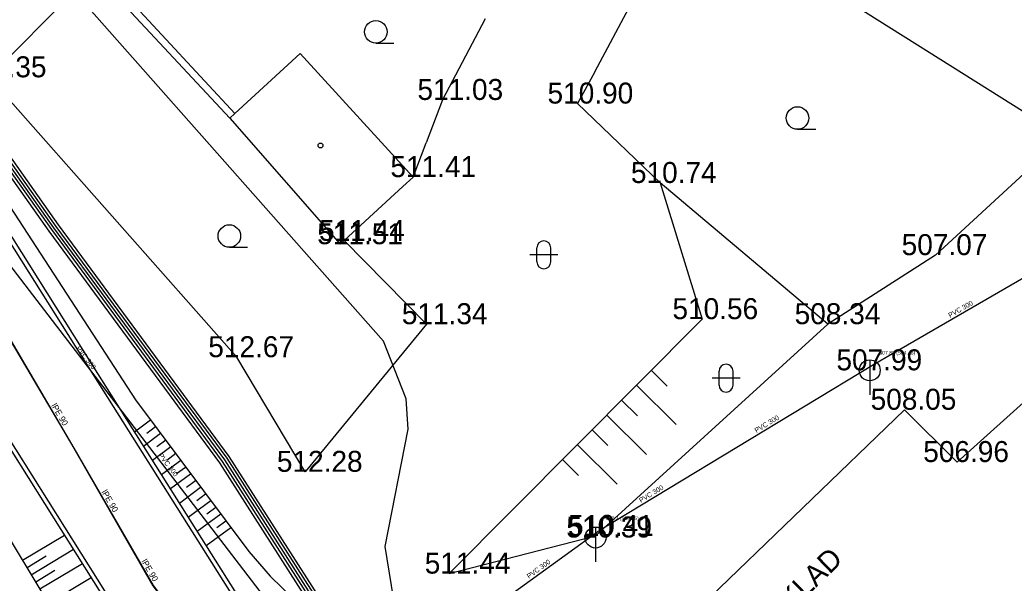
# Model space of a CAD drawing. Extents: x -668867 to -667827, y -1131943 to -1131019.
# Drawn here: x -668363.35 to -668327.77, y -1131384.01 to -1131363.87 of the extents above; entities that cross this region are included whole.
import ezdxf

# ---------------------------------------------------------------- set-up
doc = ezdxf.new("R2010")
doc.units = 0
for name, color, linetype in [('G_Bod_tecka', 7, 'Continuous'), ('G_Bod_vyska', 7, 'Continuous'), ('G_Breh_Teren', 7, 'Continuous'), ('G_Budovy-znacky', 7, 'Continuous'), ('G_Budovy_Objekty', 7, 'Continuous'), ('G_Budovy_vstupy', 7, 'Continuous'), ('G_Cesty_Schody', 7, 'Continuous'), ('G_Plochy_zpevnene', 7, 'Continuous'), ('G_Ploty', 7, 'Continuous'), ('G_Ploty_vstupy', 7, 'Continuous'), ('G_Poznamky_odkaz', 7, 'Continuous'), ('G_Site-kanalizace', 7, 'Continuous'), ('G_Vyskove_srafy', 7, 'Continuous'), ('G_Z_CHRANICKA-TEPLOVOD_kotovane', 7, 'Continuous'), ('G_Z_ELsilove_podz_kotovane', 7, 'Continuous'), ('G_Z_ELsilove_zrusene', 7, 'Continuous'), ('G_Z_KANAL_podz_kotovane', 7, 'Continuous'), ('G_Z_SPOJE_podz_kotovane', 7, 'Continuous'), ('G_Z_VODA_podz_kotovane', 7, 'Continuous'), ('G_Zelen-Znacky', 7, 'Continuous'), ('Vrstva 13', 7, 'Continuous'), ('Vrstva 2', 7, 'Continuous'), ('Vrstva 26', 7, 'Continuous'), ('Vrstva 3', 7, 'Continuous'), ('Vrstva 4', 7, 'Continuous'), ('Vrstva 8', 7, 'Continuous')]:
    doc.layers.add(name, color=color, linetype=linetype)

msp = doc.modelspace()

# ---------------------------------------------------------------- linework, layer by layer
at = {"layer": 'G_Bod_tecka'}
for p, q in [((-668348.22, -1131366.73), (-668348.22, -1131366.73)), ((-668343.4, -1131366.86), (-668343.4, -1131366.86)), ((-668349.27, -1131369.49), (-668349.27, -1131369.49)), ((-668340.44, -1131369.7), (-668340.44, -1131369.7)), ((-668351.89, -1131371.89), (-668351.89, -1131371.89)), ((-668351.76, -1131371.77), (-668351.76, -1131371.77)), ((-668330.59, -1131372.28), (-668330.59, -1131372.28)), ((-668348.8, -1131374.75), (-668348.8, -1131374.75)), ((-668338.94, -1131374.57), (-668338.94, -1131374.57)), ((-668334.44, -1131374.75), (-668334.44, -1131374.75)), ((-668355.58, -1131375.93), (-668355.58, -1131375.93)), ((-668332.94, -1131376.4), (-668332.94, -1131376.4)), ((-668331.7, -1131377.81), (-668331.7, -1131377.81)), ((-668329.81, -1131379.68), (-668329.81, -1131379.68)), ((-668353.14, -1131380.03), (-668353.14, -1131380.03)), ((-668342.75, -1131382.32), (-668342.75, -1131382.32)), ((-668342.75, -1131382.38), (-668342.75, -1131382.38)), ((-668347.99, -1131383.67), (-668347.99, -1131383.67))]:
    msp.add_line(p, q, dxfattribs=at)
at = {"layer": 'G_Breh_Teren'}
for p, q in [((-668364.19, -1131369.81), (-668359.21, -1131377.46)), ((-668338.94, -1131374.57), (-668347.99, -1131383.67)), ((-668342.75, -1131382.32), (-668334.44, -1131374.75)), ((-668359.21, -1131377.46), (-668355.16, -1131382.88)), ((-668358.86, -1131390.44), (-668364.64, -1131380.88)), ((-668347.99, -1131383.67), (-668342.75, -1131382.32))]:
    msp.add_line(p, q, dxfattribs=at)
for points in [[(-668340.44, -1131369.7), (-668338.94, -1131374.57)], [(-668355.16, -1131382.88), (-668354.39, -1131383.76), (-668353.55, -1131384.59), (-668352.66, -1131385.35), (-668351.73, -1131386.06), (-668350.74, -1131386.69), (-668349.72, -1131387.26), (-668348.66, -1131387.76), (-668347.57, -1131388.18), (-668346.45, -1131388.53), (-668345.31, -1131388.8), (-668344.15, -1131389), (-668342.99, -1131389.11), (-668342.38, -1131389.14)]]:
    msp.add_lwpolyline(points, dxfattribs=at)
at = {"layer": 'G_Budovy-znacky'}
msp.add_circle((-668352.59, -1131368.36), 0.0875, dxfattribs=at)
at = {"layer": 'G_Budovy_Objekty'}
for p, q in [((-668353.32, -1131365.07), (-668355.65, -1131367.21)), ((-668353.32, -1131365.07), (-668349.27, -1131369.49)), ((-668355.65, -1131367.21), (-668355.83, -1131367.38)), ((-668355.83, -1131367.38), (-668351.89, -1131371.89)), ((-668349.64, -1131369.82), (-668349.27, -1131369.49)), ((-668351.74, -1131371.76), (-668351.44, -1131371.48)), ((-668351.89, -1131371.89), (-668351.74, -1131371.76)), ((-668329.81, -1131379.68), (-668325.18, -1131375.51)), ((-668342.74, -1131388.45), (-668331.7, -1131377.81)), ((-668331.7, -1131377.81), (-668329.81, -1131379.68))]:
    msp.add_line(p, q, dxfattribs=at)
at = {"layer": 'G_Budovy_vstupy'}
msp.add_line((-668351.44, -1131371.48), (-668349.64, -1131369.82), dxfattribs=at)
at = {"layer": 'G_Cesty_Schody'}
for points in [[(-668355.04, -1131385.56), (-668360.89, -1131376.27), (-668365.67, -1131368.69), (-668366.59, -1131367.37), (-668378.77, -1131351.46), (-668388.76, -1131338.33)], [(-668391.56, -1131341.09), (-668381.8, -1131353.8), (-668369.6, -1131369.69), (-668368.3, -1131371.62), (-668363.5, -1131379.22), (-668357.66, -1131388.52)]]:
    msp.add_lwpolyline(points, dxfattribs=at)
at = {"layer": 'G_Plochy_zpevnene'}
for points in [[(-668354.91, -1131385.48), (-668360.76, -1131376.19), (-668365.54, -1131368.6), (-668366.47, -1131367.28), (-668378.65, -1131351.37), (-668388.64, -1131338.24)], [(-668392.25, -1131341.82), (-668391.58, -1131341.3), (-668381.92, -1131353.89), (-668369.72, -1131369.78), (-668368.43, -1131371.71), (-668363.63, -1131379.3), (-668357.79, -1131388.6)]]:
    msp.add_lwpolyline(points, dxfattribs=at)
at = {"layer": 'G_Ploty'}
for p, q in [((-668339.43, -1131359.6), (-668326, -1131368.05)), ((-668355.65, -1131367.21), (-668360.52, -1131361.98)), ((-668360.71, -1131362.15), (-668355.83, -1131367.38)), ((-668364.45, -1131365.92), (-668361.63, -1131363.08)), ((-668346.7, -1131363.83), (-668348.22, -1131366.73)), ((-668355.58, -1131375.93), (-668364.45, -1131365.92)), ((-668348.22, -1131366.73), (-668348.81, -1131368.27)), ((-668340.44, -1131369.7), (-668343.4, -1131366.86)), ((-668326, -1131368.05), (-668330.59, -1131372.28)), ((-668334.44, -1131374.75), (-668340.44, -1131369.7)), ((-668351.74, -1131371.76), (-668348.8, -1131374.75)), ((-668330.59, -1131372.28), (-668334.44, -1131374.75)), ((-668348.8, -1131374.75), (-668353.14, -1131380.03)), ((-668353.14, -1131380.03), (-668355.58, -1131375.93))]:
    msp.add_line(p, q, dxfattribs=at)
msp.add_lwpolyline([(-668342.78, -1131365.72), (-668339.87, -1131360.27), (-668339.43, -1131359.6)], dxfattribs=at)
at = {"layer": 'G_Ploty_vstupy'}
for p, q in [((-668342.78, -1131365.72), (-668343.4, -1131366.86)), ((-668349.27, -1131369.49), (-668348.81, -1131368.27))]:
    msp.add_line(p, q, dxfattribs=at)
at = {"layer": 'G_Site-kanalizace'}
for p, q in [((-668332.94, -1131376.025), (-668332.94, -1131377.275)), ((-668342.75, -1131382.005), (-668342.75, -1131383.255))]:
    msp.add_line(p, q, dxfattribs=at)
for centre in [(-668332.94, -1131376.4), (-668342.75, -1131382.38)]:
    msp.add_circle(centre, 0.375, dxfattribs=at)
at = {"layer": 'G_Vyskove_srafy'}
for p, q in [((-668340.76, -1131376.4), (-668340.19, -1131376.97)), ((-668341.29, -1131376.93), (-668339.87, -1131378.34)), ((-668341.82, -1131377.47), (-668341.25, -1131378.03)), ((-668342.34, -1131378), (-668340.93, -1131379.41)), ((-668358.67, -1131378.18), (-668359.24, -1131378.61)), ((-668358.31, -1131378.66), (-668358.92, -1131379.12)), ((-668358.49, -1131378.42), (-668358.81, -1131378.66)), ((-668342.87, -1131378.53), (-668342.31, -1131379.09)), ((-668358.13, -1131378.9), (-668358.45, -1131379.14)), ((-668343.4, -1131379.06), (-668341.98, -1131380.47)), ((-668357.95, -1131379.14), (-668358.6, -1131379.63)), ((-668357.77, -1131379.38), (-668358.09, -1131379.62)), ((-668357.59, -1131379.62), (-668358.28, -1131380.14)), ((-668343.93, -1131379.59), (-668343.36, -1131380.16)), ((-668357.24, -1131380.11), (-668357.96, -1131380.64)), ((-668357.42, -1131379.87), (-668357.74, -1131380.1)), ((-668357.06, -1131380.35), (-668357.38, -1131380.59)), ((-668356.88, -1131380.59), (-668357.64, -1131381.16)), ((-668356.7, -1131380.83), (-668357.02, -1131381.07)), ((-668356.52, -1131381.07), (-668357.32, -1131381.66)), ((-668356.16, -1131381.55), (-668357, -1131382.17)), ((-668356.34, -1131381.31), (-668356.66, -1131381.55)), ((-668355.98, -1131381.79), (-668356.3, -1131382.03)), ((-668355.8, -1131382.03), (-668356.68, -1131382.68)), ((-668363.25, -1131383.19), (-668361.75, -1131382.29)), ((-668362.94, -1131383.71), (-668361.43, -1131382.8)), ((-668363.09, -1131383.45), (-668362.41, -1131383.04)), ((-668362.63, -1131384.22), (-668361.11, -1131383.31)), ((-668362.78, -1131383.96), (-668362.1, -1131383.55)), ((-668362.32, -1131384.73), (-668360.8, -1131383.81))]:
    msp.add_line(p, q, dxfattribs=at)
at = {"layer": 'G_Z_CHRANICKA-TEPLOVOD_kotovane'}
msp.add_lwpolyline([(-668366.49, -1131364.819), (-668361.978, -1131371.193), (-668355.865, -1131379.487), (-668350.614, -1131387.7), (-668350.613, -1131387.701), (-668349.219, -1131389.792), (-668342.973, -1131397.546), (-668337.629, -1131404.464), (-668337.551, -1131404.399), (-668337.188, -1131404.096), (-668336.932, -1131404.404), (-668337.307, -1131404.716), (-668337.691, -1131405.036), (-668343.287, -1131397.794), (-668349.541, -1131390.028), (-668350.946, -1131387.92), (-668350.947, -1131387.919), (-668356.195, -1131379.713), (-668362.302, -1131371.427), (-668366.81, -1131365.061)], dxfattribs=at)
at = {"layer": 'G_Z_ELsilove_podz_kotovane'}
for points in [[(-668408.95, -1131333.1), (-668406.83, -1131330.34), (-668406.29, -1131329.53), (-668406.257, -1131329.495), (-668405.49, -1131328.67), (-668399.24, -1131323.79), (-668397.09, -1131324.16), (-668396.08, -1131324.9), (-668391.49, -1131330.34), (-668386.5, -1131336.42), (-668385.67, -1131337.67), (-668385.49, -1131339.6), (-668385.39, -1131341.8), (-668384.66, -1131342.96), (-668373.89, -1131355.96), (-668366.65, -1131364.94), (-668362.14, -1131371.31), (-668356.03, -1131379.6), (-668350.78, -1131387.81), (-668349.38, -1131389.91), (-668343.13, -1131397.67), (-668337.721, -1131404.671), (-668337.216, -1131404.25), (-668337.06, -1131404.25)], [(-668366.73, -1131365), (-668362.221, -1131371.369), (-668356.112, -1131379.657), (-668350.864, -1131387.865), (-668349.461, -1131389.969), (-668343.209, -1131397.732), (-668336.778, -1131406.053), (-668329.236, -1131414.915), (-668325.613, -1131419.198), (-668318.049, -1131426.672), (-668308.959, -1131435.142)], [(-668366.57, -1131364.88), (-668362.059, -1131371.251), (-668355.948, -1131379.543), (-668350.696, -1131387.755), (-668349.299, -1131389.851), (-668343.051, -1131397.608), (-668336.622, -1131405.927), (-668329.084, -1131414.785), (-668325.467, -1131419.062), (-668317.911, -1131426.528), (-668308.821, -1131434.998)]]:
    msp.add_lwpolyline(points, dxfattribs=at)
at = {"layer": 'G_Z_ELsilove_zrusene'}
msp.add_lwpolyline([(-668307.243, -1131431.203), (-668317.995, -1131419.84), (-668326.659, -1131411.121), (-668334.853, -1131402.182), (-668341.39, -1131394.475), (-668345.534, -1131389.961), (-668348.109, -1131387.508), (-668349.338, -1131386.039), (-668349.614, -1131385.544), (-668349.891, -1131385.05), (-668350.277, -1131382.705), (-668349.451, -1131378.507), (-668349.526, -1131377.414), (-668350.334, -1131375.359), (-668361.51, -1131362.724), (-668372.64, -1131350.72)], dxfattribs=at)
msp.add_lwpolyline([(-668307.243, -1131431.203), (-668317.995, -1131419.84), (-668326.659, -1131411.121), (-668334.853, -1131402.182), (-668341.39, -1131394.475), (-668345.534, -1131389.961), (-668348.109, -1131387.508), (-668349.338, -1131386.039), (-668349.614, -1131385.544), (-668349.891, -1131385.05), (-668350.277, -1131382.705), (-668349.451, -1131378.507), (-668349.526, -1131377.414), (-668350.334, -1131375.359), (-668361.51, -1131362.724), (-668372.64, -1131350.72)], dxfattribs=at)
at = {"layer": 'G_Z_KANAL_podz_kotovane'}
for p, q in [((-668377.82, -1131354.24), (-668351.51, -1131388.55)), ((-668342.59, -1131382.11), (-668332.8, -1131376.19)), ((-668351.51, -1131388.55), (-668342.59, -1131382.11))]:
    msp.add_line(p, q, dxfattribs=at)
msp.add_lwpolyline([(-668332.8, -1131376.19), (-668325.98, -1131372.25), (-668320.61, -1131365.08)], dxfattribs=at)
at = {"layer": 'G_Z_SPOJE_podz_kotovane'}
for points in [[(-668366.491, -1131364.82), (-668361.978, -1131371.193), (-668355.865, -1131379.486), (-668350.612, -1131387.7), (-668349.218, -1131389.791), (-668342.973, -1131397.546), (-668336.544, -1131405.864), (-668329.008, -1131414.72), (-668325.393, -1131418.994), (-668317.841, -1131426.455), (-668308.752, -1131434.926)], [(-668366.65, -1131364.94), (-668362.14, -1131371.31), (-668356.03, -1131379.6), (-668350.78, -1131387.81), (-668349.38, -1131389.91), (-668343.13, -1131397.67), (-668336.7, -1131405.99), (-668329.16, -1131414.85), (-668325.54, -1131419.13), (-668317.98, -1131426.6), (-668308.89, -1131435.07)], [(-668366.65, -1131364.94), (-668362.14, -1131371.31), (-668356.03, -1131379.6), (-668350.78, -1131387.81), (-668349.38, -1131389.91), (-668343.13, -1131397.67), (-668336.7, -1131405.99), (-668329.16, -1131414.85), (-668325.54, -1131419.13), (-668317.98, -1131426.6), (-668308.89, -1131435.07)]]:
    msp.add_lwpolyline(points, dxfattribs=at)
at = {"layer": 'G_Z_VODA_podz_kotovane'}
msp.add_lwpolyline([(-668371.54, -1131366.16), (-668371.4, -1131366.07), (-668370.38, -1131365.25), (-668367.57, -1131368.89), (-668364.45, -1131374.04), (-668361.42, -1131379.18), (-668358.58, -1131384.1), (-668354.88, -1131388.99), (-668350.92, -1131393.63), (-668343.05, -1131402.42), (-668337.87, -1131408.31), (-668331.71, -1131415.7), (-668327.79, -1131420.6)], dxfattribs=at)
at = {"layer": 'G_Zelen-Znacky'}
for p, q in [((-668350.612, -1131364.7), (-668349.962, -1131364.697)), ((-668335.522, -1131367.78), (-668334.872, -1131367.777)), ((-668355.852, -1131372), (-668355.202, -1131371.997)), ((-668338.33, -1131376.93), (-668338.33, -1131376.43)), ((-668337.83, -1131376.93), (-668337.83, -1131376.43)), ((-668337.58, -1131376.68), (-668338.58, -1131376.68))]:
    msp.add_line(p, q, dxfattribs=at)
for points in [[(-668344.1, -1131372.27), (-668345.1, -1131372.27)], [(-668344.85, -1131372.52), (-668344.85, -1131372.02)], [(-668344.35, -1131372.52), (-668344.35, -1131372.02)]]:
    msp.add_lwpolyline(points, dxfattribs=at)
for centre in [(-668350.612, -1131364.297), (-668335.522, -1131367.377), (-668355.852, -1131371.597)]:
    msp.add_circle(centre, 0.403, dxfattribs=at)
for centre, start, end in [((-668344.599, -1131372.02), 0, 180), ((-668344.599, -1131372.52), 180, 0), ((-668338.08, -1131376.43), 0, 180), ((-668338.08, -1131376.93), 180, 0)]:
    msp.add_arc(centre, 0.25, start, end, dxfattribs=at)
at = {"layer": 'Vrstva 13'}
for p, q in [((-668377.82, -1131354.24), (-668351.51, -1131388.55)), ((-668342.59, -1131382.11), (-668332.8, -1131376.19)), ((-668351.51, -1131388.55), (-668342.59, -1131382.11))]:
    msp.add_line(p, q, dxfattribs=at)
msp.add_lwpolyline([(-668332.8, -1131376.19), (-668325.98, -1131372.25), (-668320.61, -1131365.08)], dxfattribs=at)
at = {"layer": 'Vrstva 26'}
msp.add_lwpolyline([(-668371.539, -1131366.156), (-668371.405, -1131366.074), (-668370.38, -1131365.247), (-668367.57, -1131368.894), (-668364.452, -1131374.041), (-668361.418, -1131379.182), (-668358.584, -1131384.105), (-668354.881, -1131388.995), (-668350.925, -1131393.632), (-668343.054, -1131402.423), (-668337.866, -1131408.307), (-668331.706, -1131415.695), (-668327.786, -1131420.6)], dxfattribs=at)
at = {"layer": 'Vrstva 8'}
for p, q in [((-668332.8, -1131376.19), (-668332.8, -1131376.19)), ((-668342.59, -1131382.11), (-668342.59, -1131382.11))]:
    msp.add_line(p, q, dxfattribs=at)

# ---------------------------------------------------------------- texts
at = {"layer": 'G_Bod_vyska'}
for s, p in [('513.35', (-668365.462, -1131365.92)), ('511.03', (-668349.122, -1131366.73)), ('510.90', (-668344.468, -1131366.86)), ('511.41', (-668350.089, -1131369.49)), ('510.74', (-668341.484, -1131369.7)), ('511.51', (-668352.709, -1131371.89)), ('511.44', (-668352.641, -1131371.77)), ('507.07', (-668331.797, -1131372.28)), ('511.34', (-668349.681, -1131374.75)), ('510.56', (-668339.998, -1131374.57)), ('508.34', (-668335.626, -1131374.75)), ('512.67', (-668356.606, -1131375.93)), ('507.99', (-668334.13, -1131376.4)), ('508.05', (-668332.907, -1131377.81)), ('506.96', (-668331.025, -1131379.68)), ('512.28', (-668354.152, -1131380.03)), ('510.41', (-668343.732, -1131382.32)), ('510.39', (-668343.796, -1131382.38)), ('511.44', (-668348.861, -1131383.67))]:
    msp.add_text(s, height=0.75, dxfattribs=at).set_placement(p)
at = {"layer": 'G_Poznamky_odkaz'}
msp.add_text('BET. ZÁKLAD', height=0.75, rotation=43.943, dxfattribs=at).set_placement((-668338.472, -1131387.659))
at = {"layer": 'Vrstva 2'}
for s, p in [('507.86 (504.46)', (-668332.595, -1131375.837)), ('510.3 (506.95)', (-668342.385, -1131381.757))]:
    msp.add_text(s, height=0.13163, dxfattribs=at).set_placement(p)
at = {"layer": 'Vrstva 3'}
for rotation, p in [(29.9703, (-668330.065, -1131374.528)), (307.4816, (-668361.341, -1131375.614)), (31.162, (-668336.992, -1131378.642)), (307.4483, (-668358.399, -1131379.45)), (31.162, (-668341.127, -1131381.143)), (35.8361, (-668345.131, -1131383.857))]:
    msp.add_text('PVC 300', height=0.1755, rotation=rotation, dxfattribs=at).set_placement(p)
at = {"layer": 'Vrstva 4'}
for rotation, p in [(300.5139, (-668362.234, -1131377.661)), (299.9315, (-668360.434, -1131380.751)), (299.8906, (-668359.006, -1131383.23))]:
    msp.add_text('lPE 90', height=0.2194, rotation=rotation, dxfattribs=at).set_placement(p)

doc.saveas('drawing.dxf')
